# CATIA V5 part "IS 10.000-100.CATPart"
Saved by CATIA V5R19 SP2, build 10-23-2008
Part number: IS 10.000-100
Bounding box of the stored display mesh (mm): x -97.324 to 97.324, y -97.5 to 97.5, z 0 to 360
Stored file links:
  C:\Users\Bora\Desktop\3D Katı model\IS serisi\IS 10.000\IS 10.000-100.CATPart
  C:\Program Files\Dassault Systemes\B19\intel_a\reffiles\standard\MetricThickPitch.txt
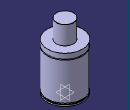
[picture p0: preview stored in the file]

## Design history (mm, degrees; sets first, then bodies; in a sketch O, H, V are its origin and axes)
Body1 (main body)
  Sketch1 on yz-plane, origin (0, 0, 0), H (0, 1, 0), V (0, 0, 1)
    point P1 (97.5, 229)
    point P2 (97.5, 224)
    point P5 (47.5, 359)
    point P7 (47.5, 359)
    point P12 (97.5, 224)
    point P13 (97.5, 229)
    arc A1 centre (97.5, 226.5) radius 2.5 from (97.5, 229) to (97.5, 224) ccw
    line L1 (97.5, 0) -> (97.5, 8)
    line L2 (47.5, 359) -> (47.5, 257)
    arc A2 centre (46.5, 359) radius 1 from (47.5, 359) to (46.5, 360) ccw
    line L3 (93.5, 16) -> (93.5, 8)
    line L4 (97.5, 16) -> (97.5, 224)
    line L5 (97.5, 229) -> (97.5, 257)
    line L6 (46.5, 360) -> (0, 360)
    point P15 (0, 360)
    line L7 (47.5, 257) -> (97.5, 257)
    line L8 (93.5, 16) -> (97.5, 16)
    line L9 (93.5, 8) -> (97.5, 8)
    line L10 (97.5, 0) -> (0, 0)
    tangency: L6 A2
    coincidence: P15 V, P1 P13, P2 P12, P5 P7
    horizontal: L7 H, L8 H, L9 H, L10 H
  Shaft1: profile Sketch1, axis Sketch1.V, angle 360
  Sketch2 on face of Shaft1 from Sketch1.L10, origin (0, 0, 0), H (1, 0, 0), V (0, -1, 0)
    point P1 (60, 0)
    distance P1 V = 60
  Hole1: placed by Sketch2, at (60, 0, 0) direction (0, 0, 1), diameter 10.106, depth 16, threaded "M12", thread diameter 12, thread depth 16, pitch 1.75
  CircPattern1: of Hole1, instances 4, angular step 90, axis from xy-plane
